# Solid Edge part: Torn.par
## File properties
Author: haldur
Template: Normal.par
Last saved by: haldur
Revision: 4
Application: Solid Edge
Accuracy: 0,990
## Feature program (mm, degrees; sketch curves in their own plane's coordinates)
lofted protrusion "unnamed LoftedProtrusion 1"
lofted protrusion "unnamed LoftedProtrusion 2"
mirror "unnamed Mirror 1" of "unnamed LoftedProtrusion 2" about plane through (0, 0, 0) normal (1, 0, 0)
lofted protrusion "unnamed LoftedProtrusion 3"
fillet "unnamed Round 1"
fillet "Round_2" radius 0.5
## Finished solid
Body 1: solid body, 12 faces, 26 edges, 17 vertices.
  Faces by surface: spline 6, plane 4, cylinder 2
  Edges by curve: line 9, curve on surface 7, intersection 6, spline 4
Bounding box of the edges (mm; curved faces can reach further): 40.009 x 37.891 x 26.369, from (-20.0081, -1.7817, 0) to (20.0007, 36.1089, 26.3685).
Cylindrical faces by radius (mm): R0.5 x2
Planar faces by outward normal: +x 1, -x 1, -z 2
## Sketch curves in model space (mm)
spline (20, 32.857, 25) -> (20, 34.4576, 25.5193) -> (20, 36.2965, 25)
line (20, 32.857, 25) -> (20, 36.2965, 25)
spline (0, 14.0895, 25) -> (0, 19.424, 26.3617) -> (0, 24.8659, 25)
line (0, 17.1374, 25) -> (0, 24.8659, 25)
line (0, 17.1374, 25) -> (0, 14.0895, 25)
spline (0, 14.8357, 25) -> (2.0804, 17.9436, 25) -> (0, 19.439, 25)
spline (0, 14.8357, 25) -> (-2.0804, 17.9436, 25) -> (0, 19.439, 25)
spline (0, -1.7817, 0) -> (5.2341, 2.6976, 0) -> (0, 6.2011, 0)
spline (0, -1.7817, 0) -> (-5.2341, 2.6976, 0) -> (0, 6.2011, 0)
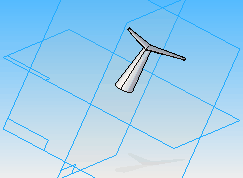
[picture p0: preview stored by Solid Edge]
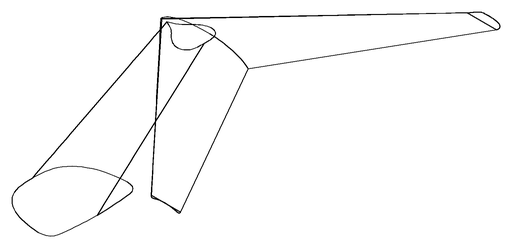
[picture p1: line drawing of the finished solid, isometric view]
